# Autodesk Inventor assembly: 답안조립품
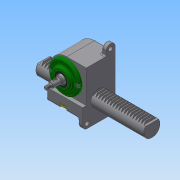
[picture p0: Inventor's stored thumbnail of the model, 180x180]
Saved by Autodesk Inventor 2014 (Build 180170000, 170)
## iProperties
Created: 2019-06
Part Number: 답안조립품
Document SubType Name: Assembly
Designer: user
Author: user
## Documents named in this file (10)
- C:\Users\user\Desktop\390604V1003\답안조립품.iam
- C:\Users\user\Desktop\390604V1003\본체.ipt
- C:\Users\user\Desktop\390604V1003\볼트 M4.ipt
- C:\Users\user\Desktop\390604V1003\앞커버.ipt
- C:\Users\user\Desktop\390604V1003\오일 실 17 30 5.ipt
- C:\Users\user\Desktop\390604V1003\피니언.ipt
- C:\Users\user\Desktop\390604V1003\누름쇠.ipt
- C:\Users\user\Desktop\390604V1003\뒤커버.ipt
- C:\Users\user\Desktop\390604V1003\래크.ipt
- C:\Users\user\Desktop\390604V1003\베어링 6003.ipt
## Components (1 placed, 1 different names)
1. 피니언:1
